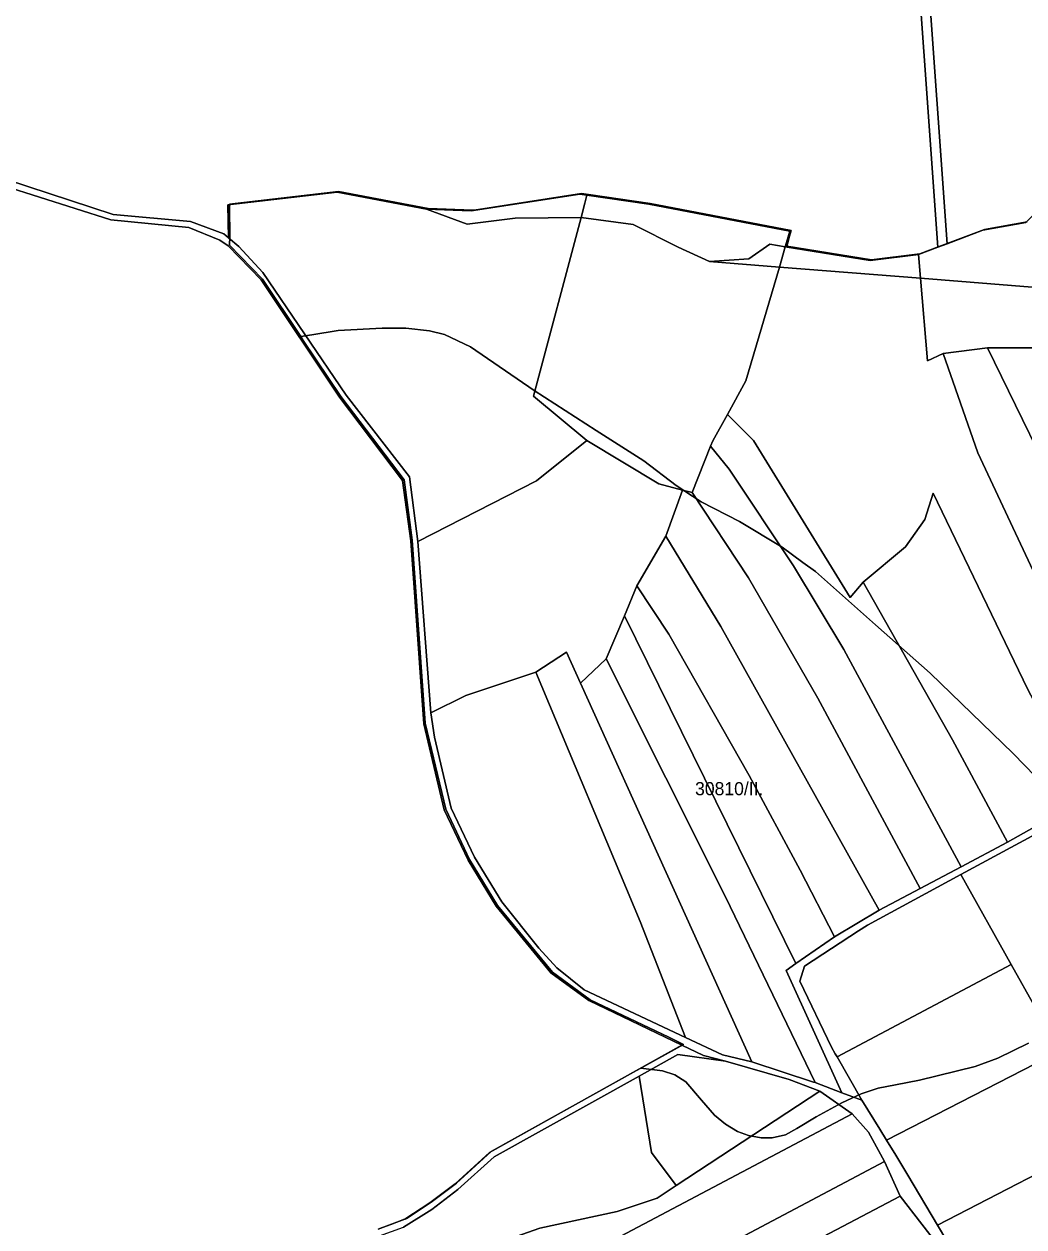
# Model space of a CAD drawing. Extents: x -535894 to -532834, y -1165802 to -1163645.
# Drawn here: x -535071.1 to -534690.2, y -1164561.1 to -1164103.1 of the extents above; entities that cross this region are included whole.
import ezdxf

# ---------------------------------------------------------------- set-up
doc = ezdxf.new("R2010")
doc.units = 0
for name, color, linetype in [('95560013', 7, 'Continuous'), ('95610013', 7, 'Continuous'), ('95620013', 7, 'Continuous'), ('95640013', 7, 'Continuous'), ('95660013', 7, 'Continuous')]:
    doc.layers.add(name, color=color, linetype=linetype)

msp = doc.modelspace()

# ---------------------------------------------------------------- linework, layer by layer
at = {"layer": '95560013'}
for points in [[(-534951.85, -1164167.07), (-534917.74, -1164173.57), (-534902.24, -1164179.24), (-534883.98, -1164176.96), (-534858.94, -1164176.7), (-534877.07, -1164244.78), (-534856.73, -1164261.58), (-534875.86, -1164276.92), (-534921.15, -1164300.08), (-534924.21, -1164275.5), (-534948.43, -1164244.35), (-534980.14, -1164197.64), (-534989.29, -1164187.7), (-534993.22, -1164184.39), (-534993.44, -1164171.93)], [(-534858.94, -1164176.7), (-534839.04, -1164179.37), (-534822, -1164188.03), (-534810.06, -1164193.46), (-534783.41, -1164195.59), (-534796.15, -1164238.96), (-534803.19, -1164251.66), (-534808.78, -1164261.74), (-534809.59, -1164263.76), (-534816.62, -1164281.45), (-534820.28, -1164280.47), (-534829.26, -1164278.07), (-534856.73, -1164261.58), (-534877.07, -1164244.78)], [(-534783.41, -1164195.59), (-534729.66, -1164199.87), (-534726.97, -1164231.26), (-534720.99, -1164228.44), (-534707.84, -1164266.29), (-534650.37, -1164388.64), (-534666.96, -1164397.98), (-534688.94, -1164356.11), (-534724.82, -1164281.62), (-534728, -1164291.7), (-534735.4, -1164302.05), (-534751.45, -1164315.56), (-534756.49, -1164321.41), (-534793.3, -1164261.64), (-534803.19, -1164251.66), (-534796.15, -1164238.96)], [(-534729.66, -1164199.87), (-534630.4, -1164207.78), (-534641.63, -1164209.34), (-534663.54, -1164225.41), (-534685.41, -1164226.35), (-534704.16, -1164226.38), (-534720.99, -1164228.44), (-534726.97, -1164231.26)], [(-534704.16, -1164226.38), (-534672.04, -1164292.08), (-534631.34, -1164377.92), (-534650.37, -1164388.64), (-534707.84, -1164266.29), (-534720.99, -1164228.44)], [(-534685.41, -1164226.35), (-534676.36, -1164241.4), (-534651.82, -1164287.55), (-534613.33, -1164365.78), (-534631.34, -1164377.92), (-534672.04, -1164292.08), (-534704.16, -1164226.38)], [(-534793.3, -1164261.64), (-534756.49, -1164321.41), (-534751.45, -1164315.56), (-534717.41, -1164375.63), (-534696.51, -1164414.6), (-534714.14, -1164423.92), (-534758.85, -1164341.14), (-534778.05, -1164309.36), (-534802.47, -1164272.58), (-534809.59, -1164263.76), (-534808.78, -1164261.74), (-534803.19, -1164251.66)], [(-534875.86, -1164276.92), (-534856.73, -1164261.58), (-534829.26, -1164278.07), (-534820.28, -1164280.47), (-534826.58, -1164298.06), (-534837.63, -1164317), (-534842.42, -1164328.36), (-534849.36, -1164344.79), (-534859.13, -1164354.02), (-534864.46, -1164342.21), (-534876.21, -1164349.78), (-534902.82, -1164358.65), (-534916.14, -1164365.28), (-534921.15, -1164300.08)], [(-534809.59, -1164263.76), (-534802.47, -1164272.58), (-534778.05, -1164309.36), (-534758.85, -1164341.14), (-534714.14, -1164423.92), (-534729.71, -1164432.15), (-534768.7, -1164359.72), (-534795.14, -1164313.94), (-534816.62, -1164281.45)], [(-534816.62, -1164281.45), (-534795.14, -1164313.94), (-534768.7, -1164359.72), (-534729.71, -1164432.15), (-534745.42, -1164440.45), (-534805.69, -1164332.46), (-534826.58, -1164298.06), (-534820.28, -1164280.47)], [(-534728, -1164291.7), (-534724.82, -1164281.62), (-534688.94, -1164356.11), (-534666.96, -1164397.98), (-534696.51, -1164414.6), (-534717.41, -1164375.63), (-534751.45, -1164315.56), (-534735.4, -1164302.05)], [(-534826.58, -1164298.06), (-534805.69, -1164332.46), (-534745.42, -1164440.45), (-534762.46, -1164450.55), (-534775.49, -1164425.15), (-534794.91, -1164389.11), (-534825.45, -1164335.34), (-534837.63, -1164317)], [(-534837.63, -1164317), (-534825.45, -1164335.34), (-534794.91, -1164389.11), (-534775.49, -1164425.15), (-534762.46, -1164450.55), (-534777.12, -1164460.78), (-534842.42, -1164328.36)], [(-534842.42, -1164328.36), (-534777.12, -1164460.78), (-534780.87, -1164463.39), (-534759.6, -1164509.93), (-534769.82, -1164506.09), (-534803.97, -1164435.37), (-534849.36, -1164344.79)], [(-534864.46, -1164342.21), (-534859.13, -1164354.02), (-534793.9, -1164498.24), (-534805.09, -1164495.48), (-534819.12, -1164488.91), (-534836.46, -1164444.76), (-534876.21, -1164349.78)], [(-534849.36, -1164344.79), (-534803.97, -1164435.37), (-534769.82, -1164506.09), (-534770.38, -1164505.88), (-534793.9, -1164498.24), (-534859.13, -1164354.02)], [(-534876.21, -1164349.78), (-534836.46, -1164444.76), (-534819.12, -1164488.91), (-534857.75, -1164470.83), (-534868.09, -1164462.44), (-534875.04, -1164454.94), (-534889.06, -1164437.27), (-534899.57, -1164420.22), (-534908.44, -1164401.64), (-534914.8, -1164374.59), (-534916.14, -1164365.28), (-534902.82, -1164358.65)], [(-534714.26, -1164426.9), (-534663.27, -1164399.34), (-534631.7, -1164457.63), (-534591.62, -1164539.75), (-534575.39, -1164577.77), (-534548.57, -1164664.74), (-534529.51, -1164742.37), (-534519.96, -1164775.85), (-534512.61, -1164811.26), (-534562.14, -1164816.82), (-534585.02, -1164716.41), (-534592.87, -1164689.03), (-534598.52, -1164669.31), (-534600.76, -1164662.66), (-534607.61, -1164642.33), (-534611.82, -1164629.82), (-534620.54, -1164603.95), (-534622.31, -1164599.78), (-534633.48, -1164573.56), (-534638.57, -1164562.2), (-534650.14, -1164541.51), (-534658.33, -1164526.87), (-534676.64, -1164494.15), (-534695.08, -1164461.19)], [(-534749.86, -1164446.14), (-534714.26, -1164426.9), (-534695.08, -1164461.19), (-534761.39, -1164496.32), (-534762.09, -1164495.12), (-534763.52, -1164492.61), (-534775.57, -1164467.46), (-534773.86, -1164461.8), (-534753.21, -1164448.33)], [(-534695.08, -1164461.19), (-534676.64, -1164494.15), (-534742.58, -1164527.98), (-534745.16, -1164523.82), (-534751.97, -1164512.8), (-534761.39, -1164496.32)], [(-534658.33, -1164526.87), (-534723.13, -1164560.41), (-534734.51, -1164541.31), (-534738.99, -1164533.78), (-534742.58, -1164527.98), (-534676.64, -1164494.15)], [(-534803.86, -1164497.99), (-534779.71, -1164504.98), (-534768.01, -1164509.35), (-534822.67, -1164545.3), (-534832.14, -1164532.75), (-534836.85, -1164503.64), (-534822.13, -1164495.45)], [(-534836.85, -1164503.64), (-534832.14, -1164532.75), (-534822.67, -1164545.3), (-534830, -1164550.13), (-534845.17, -1164555.12), (-534874.58, -1164561.46), (-534901.23, -1164570.96), (-534933.74, -1164580.6), (-534950.39, -1164582.04), (-534954.11, -1164567.3), (-534943.8, -1164566.05), (-534935.73, -1164564.46), (-534926.58, -1164561.08), (-534915.74, -1164554.41), (-534905.82, -1164546.8), (-534892.07, -1164534.38)], [(-534768.01, -1164509.35), (-534755.68, -1164518.03), (-534901.21, -1164594.89), (-534994.2, -1164614.17), (-535000.27, -1164571.83), (-534999.95, -1164571.8), (-534954.11, -1164567.3), (-534950.39, -1164582.04), (-534933.74, -1164580.6), (-534901.23, -1164570.96), (-534874.58, -1164561.46), (-534845.17, -1164555.12), (-534830, -1164550.13), (-534822.67, -1164545.3)], [(-534755.68, -1164518.03), (-534749.42, -1164524.99), (-534743.38, -1164536.18), (-534894.51, -1164616.18), (-534991.15, -1164635.45), (-534994.2, -1164614.17), (-534901.21, -1164594.89)], [(-534658.33, -1164526.87), (-534650.14, -1164541.51), (-534638.57, -1164562.2), (-534705.03, -1164590.78), (-534723.13, -1164560.41)], [(-534743.38, -1164536.18), (-534737.42, -1164549.39), (-534812.95, -1164589.11), (-534844.16, -1164606.93), (-534884.64, -1164626.55), (-534893.57, -1164628.99), (-534911.75, -1164633.96), (-534989.09, -1164649.85), (-534991.15, -1164635.45), (-534894.51, -1164616.18)]]:
    msp.add_lwpolyline(points, close=True, dxfattribs=at)
for points in [[(-534663.27, -1164399.34), (-534714.26, -1164426.9), (-534749.86, -1164446.14), (-534753.21, -1164448.33), (-534773.86, -1164461.8), (-534775.57, -1164467.46), (-534763.52, -1164492.61), (-534762.09, -1164495.12), (-534761.39, -1164496.32), (-534751.97, -1164512.8), (-534759.6, -1164509.93), (-534780.87, -1164463.39), (-534777.12, -1164460.78), (-534762.46, -1164450.55), (-534745.42, -1164440.45), (-534729.71, -1164432.15), (-534714.14, -1164423.92), (-534696.51, -1164414.6), (-534666.96, -1164397.98)], [(-534812.95, -1164589.11), (-534737.42, -1164549.39), (-534720.94, -1164570.71)]]:
    msp.add_lwpolyline(points, dxfattribs=at)
at = {"layer": '95610013'}
for points in [[(-534643.92, -1164165.11), (-534627.51, -1164173.48), (-534629.84, -1164201.15), (-534630.4, -1164207.78), (-534729.66, -1164199.87), (-534730.44, -1164190.85), (-534723.07, -1164188.05), (-534719.55, -1164186.71), (-534705.88, -1164181.51), (-534689.58, -1164178.65), (-534682.2, -1164171.34), (-534663.32, -1164170.6)], [(-534856.69, -1164168.25), (-534857.49, -1164171.28), (-534858.94, -1164176.7), (-534883.98, -1164176.96), (-534902.24, -1164179.24), (-534917.74, -1164173.57), (-534900.73, -1164174.23), (-534859.37, -1164167.86)], [(-534856.69, -1164168.25), (-534833.11, -1164171.65), (-534779.41, -1164181.96), (-534780.04, -1164184.13), (-534781.14, -1164187.86), (-534787.03, -1164186.9), (-534795.09, -1164192.41), (-534810.06, -1164193.46), (-534822, -1164188.03), (-534839.04, -1164179.37), (-534858.94, -1164176.7), (-534857.49, -1164171.28)], [(-534781.14, -1164187.86), (-534783.41, -1164195.59), (-534810.06, -1164193.46), (-534795.09, -1164192.41), (-534787.03, -1164186.9)], [(-534730.44, -1164190.85), (-534729.66, -1164199.87), (-534783.41, -1164195.59), (-534781.14, -1164187.86), (-534748.83, -1164193.12)]]:
    msp.add_lwpolyline(points, close=True, dxfattribs=at)
at = {"layer": '95620013'}
for points in [[(-534429.37, -1164029.61), (-534577.82, -1163998.3), (-534580.94, -1163997.64), (-534735.42, -1163965.07), (-534719.55, -1164186.71), (-534723.07, -1164188.05), (-534739, -1163964.32), (-535025.69, -1163903.86), (-535021.19, -1163901.16), (-534739.26, -1163960.49), (-534752.66, -1163750.06), (-534749.05, -1163747.99), (-534735.68, -1163961.24), (-534580.33, -1163993.93), (-534576.69, -1163994.7), (-534428.93, -1164025.8)], [(-535193.05, -1164004.23), (-535025.69, -1163903.86), (-534739, -1163964.32), (-534723.07, -1164188.05), (-534730.44, -1164190.85), (-534748.83, -1164193.12), (-534781.14, -1164187.86), (-534780.04, -1164184.13), (-534779.41, -1164181.96), (-534833.11, -1164171.65), (-534856.69, -1164168.25), (-534859.37, -1164167.86), (-534900.73, -1164174.23), (-534917.74, -1164173.57), (-534951.85, -1164167.07), (-534993.44, -1164171.93), (-534993.22, -1164184.39), (-534995, -1164182.89), (-535007.7, -1164178.2), (-535037.17, -1164175.56), (-535077.79, -1164162.19)], [(-535078.73, -1164164.6), (-535038.07, -1164177.61), (-535008.27, -1164180.58), (-534996.47, -1164185.37), (-534993.36, -1164187.53), (-534980.76, -1164200.5), (-534950.98, -1164245.18), (-534926.89, -1164276.88), (-534923.8, -1164299.86), (-534918.83, -1164369.44), (-534911.03, -1164402.19), (-534901.93, -1164421.42), (-534891.32, -1164438.91), (-534870.38, -1164464.28), (-534856.02, -1164474.78), (-534820.5, -1164491.79), (-534893.74, -1164532.65), (-534906.91, -1164544.6), (-534916.57, -1164551.88), (-534926.03, -1164558.08), (-534936.2, -1164561.96)]]:
    msp.add_lwpolyline(points, dxfattribs=at)
msp.add_lwpolyline([(-534735.42, -1163965.07), (-534580.94, -1163997.64), (-534577.82, -1163998.3), (-534429.37, -1164029.61), (-534426.3, -1164271.96), (-534439.05, -1164259.47), (-534446.52, -1164256.91), (-534458.72, -1164249.64), (-534465.85, -1164242.8), (-534477.05, -1164227.75), (-534492.39, -1164221.02), (-534521.68, -1164205.56), (-534554.26, -1164192.45), (-534591.23, -1164182.82), (-534594.62, -1164181.93), (-534604.82, -1164180.29), (-534627.51, -1164173.48), (-534643.92, -1164165.11), (-534663.32, -1164170.6), (-534682.2, -1164171.34), (-534689.58, -1164178.65), (-534705.88, -1164181.51), (-534719.55, -1164186.71)], close=True, dxfattribs=at)
at = {"layer": '95640013'}
for points in [[(-534720.94, -1164570.71), (-534737.42, -1164549.39), (-534743.38, -1164536.18), (-534749.42, -1164524.99), (-534755.68, -1164518.03), (-534768.01, -1164509.35), (-534779.71, -1164504.98), (-534803.86, -1164497.99), (-534812.31, -1164495.72), (-534820.5, -1164491.79), (-534856.02, -1164474.78), (-534870.38, -1164464.28), (-534891.32, -1164438.91), (-534901.93, -1164421.42), (-534911.03, -1164402.19), (-534918.83, -1164369.44), (-534923.8, -1164299.86), (-534926.89, -1164276.88), (-534950.98, -1164245.18), (-534980.76, -1164200.5), (-534993.36, -1164187.53), (-534996.47, -1164185.37), (-535008.27, -1164180.58), (-535038.07, -1164177.61), (-535078.73, -1164164.6)], [(-535077.79, -1164162.19), (-535037.17, -1164175.56), (-535007.7, -1164178.2), (-534995, -1164182.89), (-534993.22, -1164184.39), (-534989.29, -1164187.7), (-534980.14, -1164197.64), (-534948.43, -1164244.35), (-534924.21, -1164275.5), (-534921.15, -1164300.08), (-534916.14, -1164365.28), (-534914.8, -1164374.59), (-534908.44, -1164401.64), (-534899.57, -1164420.22), (-534889.06, -1164437.27), (-534875.04, -1164454.94), (-534868.09, -1164462.44), (-534857.75, -1164470.83), (-534819.12, -1164488.91), (-534805.09, -1164495.48), (-534793.9, -1164498.24), (-534770.38, -1164505.88), (-534769.82, -1164506.09), (-534759.6, -1164509.93), (-534751.97, -1164512.8), (-534745.16, -1164523.82), (-534742.58, -1164527.98), (-534738.99, -1164533.78), (-534734.51, -1164541.31), (-534723.13, -1164560.41), (-534705.03, -1164590.78)], [(-534936.2, -1164561.96), (-534926.03, -1164558.08), (-534916.57, -1164551.88), (-534906.91, -1164544.6), (-534893.74, -1164532.65), (-534820.5, -1164491.79), (-534812.31, -1164495.72), (-534803.86, -1164497.99), (-534822.13, -1164495.45), (-534836.85, -1164503.64), (-534892.07, -1164534.38), (-534905.82, -1164546.8), (-534915.74, -1164554.41), (-534926.58, -1164561.08)]]:
    msp.add_lwpolyline(points, dxfattribs=at)
at = {"layer": '95660013'}
for points in [[(-534685.81, -1164389.49), (-534694.34, -1164380.73), (-534725.95, -1164350.22), (-534746.741, -1164331.83), (-534769.679, -1164311.539), (-534774.451, -1164308.019), (-534782.34, -1164302.2), (-534798.58, -1164292.49), (-534813.16, -1164284.999), (-534822.64, -1164278.71), (-534834.98, -1164269.391), (-534853.14, -1164257.76), (-534876.848, -1164242.577), (-534901, -1164225.91), (-534910.96, -1164221.29), (-534916.61, -1164219.85), (-534925.61, -1164218.82), (-534934.669, -1164218.82), (-534951.41, -1164219.69), (-534961.495, -1164221.347), (-534965.667, -1164222.032), (-534980.193, -1164200.238), (-534992.796, -1164187.266), (-534992.657, -1164184.123), (-534992.864, -1164172.606), (-534992.881, -1164171.663), (-534951.283, -1164166.804), (-534917.176, -1164173.315), (-534900.166, -1164173.97), (-534899.694, -1164173.897), (-534858.802, -1164167.607), (-534856.129, -1164167.995), (-534832.542, -1164171.394), (-534778.846, -1164181.704), (-534779.48, -1164183.877), (-534780.07, -1164185.879), (-534780.579, -1164187.608), (-534748.266, -1164192.874), (-534729.874, -1164190.604), (-534722.509, -1164187.801), (-534705.313, -1164181.264), (-534689.018, -1164178.399)], [(-534689.018, -1164178.399), (-534705.313, -1164181.264), (-534722.509, -1164187.801), (-534729.874, -1164190.604), (-534748.266, -1164192.874), (-534780.579, -1164187.608), (-534780.07, -1164185.879), (-534779.48, -1164183.877), (-534778.846, -1164181.704), (-534832.542, -1164171.394), (-534856.129, -1164167.995), (-534858.802, -1164167.607), (-534899.694, -1164173.897), (-534900.166, -1164173.97), (-534917.176, -1164173.315), (-534951.283, -1164166.804), (-534992.881, -1164171.663), (-534992.864, -1164172.606), (-534992.657, -1164184.123), (-534992.796, -1164187.266), (-534980.193, -1164200.238), (-534965.667, -1164222.032), (-534964.702, -1164223.481), (-534950.412, -1164244.92), (-534926.32, -1164276.615), (-534923.23, -1164299.595), (-534918.262, -1164369.183), (-534910.455, -1164401.933), (-534901.354, -1164421.155), (-534890.744, -1164438.654), (-534869.801, -1164464.022), (-534855.445, -1164474.524), (-534825.523, -1164488.851), (-534819.921, -1164491.534), (-534836.099, -1164500.559), (-534837.757, -1164501.484), (-534893.16, -1164532.39), (-534906.33, -1164544.336), (-534915.983, -1164551.622), (-534925.446, -1164557.813), (-534925.946, -1164558.004), (-534930.369, -1164559.695), (-534935.616, -1164561.701)], [(-534688.52, -1164491.03), (-534700.23, -1164496.84), (-534708.87, -1164499.991), (-534730.05, -1164505.211), (-534739.126, -1164506.93), (-534745.78, -1164508.19), (-534752.19, -1164510.38), (-534759.64, -1164513.8), (-534769.44, -1164519.18), (-534776.72, -1164523.6), (-534781.1, -1164525.95), (-534786.08, -1164527.14), (-534790.38, -1164527.18), (-534795.2, -1164526.19), (-534799.317, -1164524.66), (-534803.96, -1164521.97), (-534808.069, -1164518.519), (-534813, -1164512.81), (-534819.077, -1164505.775), (-534823.27, -1164503.17), (-534827.97, -1164501.66), (-534836.099, -1164500.559), (-534819.921, -1164491.534), (-534825.523, -1164488.851), (-534855.445, -1164474.524), (-534869.801, -1164464.022), (-534890.744, -1164438.654), (-534901.354, -1164421.155), (-534910.455, -1164401.933), (-534918.262, -1164369.183), (-534923.23, -1164299.595), (-534926.32, -1164276.615), (-534950.412, -1164244.92), (-534964.702, -1164223.481), (-534965.667, -1164222.032), (-534961.495, -1164221.347), (-534951.41, -1164219.69), (-534934.669, -1164218.82), (-534925.61, -1164218.82), (-534916.61, -1164219.85), (-534910.96, -1164221.29), (-534901, -1164225.91), (-534876.848, -1164242.577), (-534853.14, -1164257.76), (-534834.98, -1164269.391), (-534822.64, -1164278.71), (-534813.16, -1164284.999), (-534798.58, -1164292.49), (-534782.34, -1164302.2), (-534774.451, -1164308.019), (-534769.679, -1164311.539), (-534746.741, -1164331.83), (-534725.95, -1164350.22), (-534694.34, -1164380.73), (-534685.81, -1164389.49)], [(-534935.616, -1164561.701), (-534930.369, -1164559.695), (-534925.946, -1164558.004), (-534925.446, -1164557.813), (-534915.983, -1164551.622), (-534906.33, -1164544.336), (-534893.16, -1164532.39), (-534837.757, -1164501.484), (-534836.099, -1164500.559), (-534827.97, -1164501.66), (-534823.27, -1164503.17), (-534819.077, -1164505.775), (-534813, -1164512.81), (-534808.069, -1164518.519), (-534803.96, -1164521.97), (-534799.317, -1164524.66), (-534795.2, -1164526.19), (-534790.38, -1164527.18), (-534786.08, -1164527.14), (-534781.1, -1164525.95), (-534776.72, -1164523.6), (-534769.44, -1164519.18), (-534759.64, -1164513.8), (-534752.19, -1164510.38), (-534745.78, -1164508.19), (-534739.126, -1164506.93), (-534730.05, -1164505.211), (-534708.87, -1164499.991), (-534700.23, -1164496.84), (-534688.52, -1164491.03)]]:
    msp.add_lwpolyline(points, dxfattribs=at)

# ---------------------------------------------------------------- texts
msp.add_text('30810/II.', height=5, rotation=360, dxfattribs=at).set_placement((-534815.503, -1164396.679))

doc.saveas('drawing.dxf')
